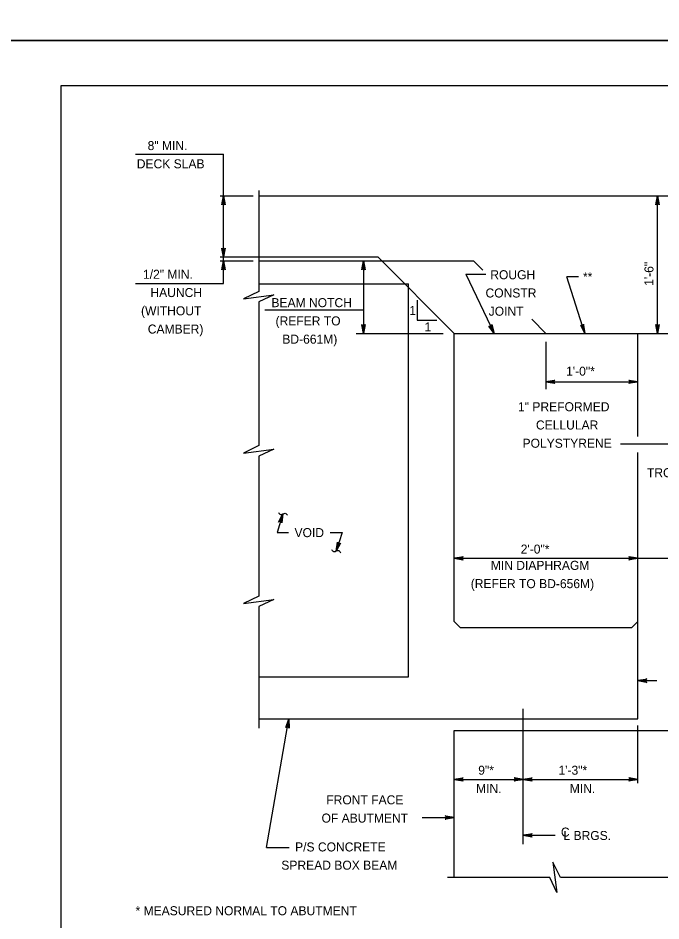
# Model space of a CAD drawing. Extents: x 636530 to 644067, y 294168 to 299122.
# Drawn here: x 639032.6 to 639246.3, y 295063.7 to 295364 of the extents above; entities that cross this region are included whole.
import ezdxf

# ---------------------------------------------------------------- set-up
doc = ezdxf.new("R2010")
doc.units = 0
doc.layers.add('1', color=7, linetype='Continuous')
doc.layers.add('PLT-BNDY', color=7, linetype='Continuous')

msp = doc.modelspace()

# ---------------------------------------------------------------- linework, layer by layer
at = {"layer": '1'}
for p, q in [((639832.78, 295341.48), (639046.78, 295341.48)), ((639046.78, 295341.48), (639046.78, 294777.48)), ((639071.67, 295318.67), (639100.84, 295318.67)), ((639100.84, 295284.5), (639100.84, 295318.67)), ((639112.67, 295306.66), (639112.67, 295273.07)), ((639099.73, 295304.82), (639110.72, 295304.82)), ((639112.67, 295304.82), (639291.18, 295304.82)), ((639245.17, 295259.1), (639245.17, 295304.82)), ((639099.73, 295284.5), (639110.72, 295284.5)), ((639099.73, 295283.23), (639110.72, 295283.23)), ((639100.84, 295275.67), (639100.84, 295284.5)), ((639106.89, 295284.5), (639152.19, 295284.5)), ((639112.67, 295283.23), (639153.46, 295283.23)), ((639147.38, 295283.23), (639147.38, 295259.1)), ((639177.59, 295259.1), (639152.19, 295284.5)), ((639153.46, 295283.23), (639183.94, 295283.23)), ((639187.05, 295280.12), (639183.94, 295283.23)), ((639181.39, 295278.76), (639190.86, 295259.1)), ((639181.39, 295278.76), (639188.12, 295278.76)), ((639218.89, 295277.94), (639215.04, 295277.94)), ((639220.95, 295259.1), (639215.04, 295277.94)), ((639071.67, 295275.67), (639100.84, 295275.67)), ((639112.67, 295275.61), (639162.35, 295275.61)), ((639162.35, 295144.8), (639162.35, 295275.61)), ((639165.21, 295270.12), (639165.21, 295263.54)), ((639112.67, 295269.55), (639112.67, 295221.79)), ((639114.61, 295266.93), (639147.38, 295266.93)), ((639165.21, 295263.54), (639171.79, 295263.54)), ((639208.07, 295259.1), (639203.4, 295263.77)), ((639145.03, 295259.1), (639173.94, 295259.1)), ((639177.59, 295259.1), (639238.55, 295259.1)), ((639177.59, 295163.21), (639177.59, 295259.1)), ((639238.55, 295259.1), (639313.34, 295259.1)), ((639238.55, 295224.8), (639238.55, 295259.1)), ((639208.07, 295256.29), (639208.07, 295240.58)), ((639208.07, 295242.99), (639238.55, 295242.99)), ((639232.79, 295222.35), (639251.5, 295222.35)), ((639238.55, 295163.21), (639238.55, 295219.43)), ((639112.67, 295218.27), (639112.67, 295171.73)), ((639120.6, 295199.03), (639118.68, 295192.82)), ((639118.68, 295192.82), (639122.48, 295192.82)), ((639136.31, 295192.82), (639140.3, 295192.82)), ((639140.3, 295192.82), (639138.38, 295186.61)), ((639177.59, 295184.27), (639296.46, 295184.27)), ((639112.67, 295168.21), (639112.67, 295127.8)), ((639177.59, 295163.21), (639179.5, 295161.31)), ((639236.65, 295161.31), (639238.55, 295163.21)), ((639238.55, 295130.83), (639238.55, 295163.21)), ((639179.5, 295161.31), (639236.65, 295161.31)), ((639112.67, 295144.8), (639162.35, 295144.8)), ((639238.55, 295143.58), (639244.95, 295143.58)), ((639200.45, 295089.18), (639200.45, 295134.26)), ((639112.67, 295130.83), (639238.55, 295130.83)), ((639115.2, 295088.03), (639122.64, 295130.83)), ((639177.59, 295127.02), (639253.79, 295127.02)), ((639177.59, 295078.06), (639177.59, 295127.02)), ((639238.55, 295109.45), (639238.55, 295128.65)), ((639177.59, 295110.74), (639200.45, 295110.74)), ((639200.45, 295110.74), (639238.55, 295110.74)), ((639166.96, 295098.04), (639177.59, 295098.04)), ((639200.45, 295092.14), (639211.08, 295092.14)), ((639115.2, 295088.03), (639122.72, 295088.03)), ((639209.35, 295078.06), (639175.31, 295078.06)), ((639261.49, 295078.06), (639212.87, 295078.06))]:
    msp.add_line(p, q, dxfattribs=at)
for points in [[(639100.84, 295304.82), (639101.4, 295301.84), (639101.32, 295301.95), (639101.24, 295302.07), (639101.14, 295302.12), (639101.04, 295302.18), (639100.94, 295302.2), (639100.84, 295302.22), (639100.74, 295302.2), (639100.64, 295302.18), (639100.54, 295302.12), (639100.44, 295302.07), (639100.36, 295301.95), (639100.28, 295301.84), (639100.84, 295304.82), (639100.36, 295301.95), (639100.44, 295302.07), (639100.84, 295304.82), (639100.54, 295302.12), (639100.64, 295302.18), (639100.84, 295304.82), (639100.74, 295302.2), (639100.84, 295302.22), (639100.84, 295304.82), (639100.94, 295302.2), (639101.04, 295302.18), (639100.84, 295304.82), (639101.14, 295302.12), (639101.24, 295302.07), (639100.84, 295304.82), (639101.32, 295301.95)], [(639245.17, 295304.82), (639245.73, 295301.84), (639245.57, 295302.07), (639245.37, 295302.18), (639245.17, 295302.22), (639244.97, 295302.18), (639244.77, 295302.07), (639244.61, 295301.84), (639245.17, 295304.82), (639244.77, 295302.07), (639244.97, 295302.18), (639245.17, 295304.82), (639245.17, 295302.22), (639245.37, 295302.18), (639245.17, 295304.82), (639245.57, 295302.07)], [(639100.84, 295284.5), (639100.28, 295287.48), (639100.36, 295287.36), (639100.44, 295287.25), (639100.54, 295287.19), (639100.64, 295287.13), (639100.74, 295287.11), (639100.84, 295287.1), (639100.94, 295287.11), (639101.04, 295287.13), (639101.14, 295287.19), (639101.24, 295287.25), (639101.32, 295287.36), (639101.4, 295287.48), (639100.84, 295284.5), (639101.32, 295287.36), (639101.24, 295287.25), (639100.84, 295284.5), (639101.14, 295287.19), (639101.04, 295287.13), (639100.84, 295284.5), (639100.94, 295287.11), (639100.84, 295287.1), (639100.84, 295284.5), (639100.74, 295287.11), (639100.64, 295287.13), (639100.84, 295284.5), (639100.54, 295287.19), (639100.44, 295287.25), (639100.84, 295284.5), (639100.36, 295287.36)], [(639100.84, 295283.23), (639101.4, 295280.25), (639101.32, 295280.36), (639101.24, 295280.48), (639101.14, 295280.54), (639101.04, 295280.59), (639100.94, 295280.61), (639100.84, 295280.63), (639100.74, 295280.61), (639100.64, 295280.59), (639100.54, 295280.54), (639100.44, 295280.48), (639100.36, 295280.36), (639100.28, 295280.25), (639100.84, 295283.23), (639100.36, 295280.36), (639100.44, 295280.48), (639100.84, 295283.23), (639100.54, 295280.54), (639100.64, 295280.59), (639100.84, 295283.23), (639100.74, 295280.61), (639100.84, 295280.63), (639100.84, 295283.23), (639100.94, 295280.61), (639101.04, 295280.59), (639100.84, 295283.23), (639101.14, 295280.54), (639101.24, 295280.48), (639100.84, 295283.23), (639101.32, 295280.36)], [(639147.38, 295283.23), (639147.94, 295280.25), (639147.86, 295280.36), (639147.78, 295280.48), (639147.68, 295280.54), (639147.58, 295280.59), (639147.48, 295280.61), (639147.38, 295280.63), (639147.28, 295280.61), (639147.18, 295280.59), (639147.08, 295280.54), (639146.98, 295280.48), (639146.9, 295280.36), (639146.82, 295280.25), (639147.38, 295283.23), (639146.9, 295280.36), (639146.98, 295280.48), (639147.38, 295283.23), (639147.08, 295280.54), (639147.18, 295280.59), (639147.38, 295283.23), (639147.28, 295280.61), (639147.38, 295280.63), (639147.38, 295283.23), (639147.48, 295280.61), (639147.58, 295280.59), (639147.38, 295283.23), (639147.68, 295280.54), (639147.78, 295280.48), (639147.38, 295283.23), (639147.86, 295280.36)], [(639112.67, 295273.07), (639107.48, 295270.53), (639117.63, 295271.91), (639112.67, 295269.55)], [(639147.38, 295259.1), (639146.82, 295262.08), (639146.9, 295261.97), (639146.98, 295261.85), (639147.08, 295261.79), (639147.18, 295261.73), (639147.28, 295261.72), (639147.38, 295261.7), (639147.48, 295261.72), (639147.58, 295261.73), (639147.68, 295261.79), (639147.78, 295261.85), (639147.86, 295261.97), (639147.94, 295262.08), (639147.38, 295259.1), (639147.86, 295261.97), (639147.78, 295261.85), (639147.38, 295259.1), (639147.68, 295261.79), (639147.58, 295261.73), (639147.38, 295259.1), (639147.48, 295261.72), (639147.38, 295261.7), (639147.38, 295259.1), (639147.28, 295261.72), (639147.18, 295261.73), (639147.38, 295259.1), (639147.08, 295261.79), (639146.98, 295261.85), (639147.38, 295259.1), (639146.9, 295261.97)], [(639190.86, 295259.1), (639189.06, 295261.54), (639189.18, 295261.47), (639189.3, 295261.4), (639189.42, 295261.39), (639189.53, 295261.38), (639189.63, 295261.41), (639189.73, 295261.44), (639189.81, 295261.5), (639189.89, 295261.56), (639189.96, 295261.66), (639190.02, 295261.75), (639190.04, 295261.89), (639190.07, 295262.03), (639190.86, 295259.1), (639190.04, 295261.89), (639190.02, 295261.75), (639190.86, 295259.1), (639189.96, 295261.66), (639189.89, 295261.56), (639190.86, 295259.1), (639189.81, 295261.5), (639189.73, 295261.44), (639190.86, 295259.1), (639189.63, 295261.41), (639189.53, 295261.38), (639190.86, 295259.1), (639189.42, 295261.39), (639189.3, 295261.4), (639190.86, 295259.1), (639189.18, 295261.47)], [(639220.95, 295259.1), (639220.59, 295262.11), (639220.55, 295261.98), (639220.5, 295261.84), (639220.43, 295261.76), (639220.35, 295261.67), (639220.26, 295261.63), (639220.17, 295261.58), (639220.07, 295261.57), (639219.97, 295261.55), (639219.85, 295261.58), (639219.74, 295261.61), (639219.63, 295261.69), (639219.52, 295261.78), (639220.95, 295259.1), (639219.63, 295261.69), (639219.74, 295261.61), (639220.95, 295259.1), (639219.85, 295261.58), (639219.97, 295261.55), (639220.95, 295259.1), (639220.07, 295261.57), (639220.17, 295261.58), (639220.95, 295259.1), (639220.26, 295261.63), (639220.35, 295261.67), (639220.95, 295259.1), (639220.43, 295261.76), (639220.5, 295261.84), (639220.95, 295259.1), (639220.55, 295261.98)], [(639245.17, 295259.1), (639244.61, 295262.08), (639244.77, 295261.85), (639244.97, 295261.73), (639245.17, 295261.7), (639245.37, 295261.73), (639245.57, 295261.85), (639245.73, 295262.08), (639245.17, 295259.1), (639245.57, 295261.85), (639245.37, 295261.73), (639245.17, 295259.1), (639245.17, 295261.7), (639244.97, 295261.73), (639245.17, 295259.1), (639244.77, 295261.85)], [(639208.07, 295242.99), (639211.06, 295243.55), (639210.94, 295243.47), (639210.83, 295243.39), (639210.77, 295243.29), (639210.71, 295243.19), (639210.69, 295243.09), (639210.67, 295242.99), (639210.69, 295242.89), (639210.71, 295242.79), (639210.77, 295242.69), (639210.83, 295242.59), (639210.94, 295242.51), (639211.06, 295242.43), (639208.07, 295242.99), (639210.94, 295242.51), (639210.83, 295242.59), (639208.07, 295242.99), (639210.77, 295242.69), (639210.71, 295242.79), (639208.07, 295242.99), (639210.69, 295242.89), (639210.67, 295242.99), (639208.07, 295242.99), (639210.69, 295243.09), (639210.71, 295243.19), (639208.07, 295242.99), (639210.77, 295243.29), (639210.83, 295243.39), (639208.07, 295242.99), (639210.94, 295243.47)], [(639238.55, 295242.99), (639235.57, 295242.43), (639235.69, 295242.51), (639235.8, 295242.59), (639235.86, 295242.69), (639235.92, 295242.79), (639235.94, 295242.89), (639235.95, 295242.99), (639235.94, 295243.09), (639235.92, 295243.19), (639235.86, 295243.29), (639235.8, 295243.39), (639235.69, 295243.47), (639235.57, 295243.55), (639238.55, 295242.99), (639235.69, 295243.47), (639235.8, 295243.39), (639238.55, 295242.99), (639235.86, 295243.29), (639235.92, 295243.19), (639238.55, 295242.99), (639235.94, 295243.09), (639235.95, 295242.99), (639238.55, 295242.99), (639235.94, 295242.89), (639235.92, 295242.79), (639238.55, 295242.99), (639235.86, 295242.69), (639235.8, 295242.59), (639238.55, 295242.99), (639235.69, 295242.51)], [(639112.67, 295221.79), (639107.48, 295219.25), (639117.63, 295220.63), (639112.67, 295218.27)], [(639120.6, 295199.03), (639120.26, 295196.02), (639120.17, 295196.29), (639120.02, 295196.46), (639119.84, 295196.55), (639119.64, 295196.58), (639119.41, 295196.52), (639119.19, 295196.35), (639120.6, 295199.03), (639119.41, 295196.52), (639119.64, 295196.58), (639120.6, 295199.03), (639119.84, 295196.55), (639120.02, 295196.46), (639120.6, 295199.03), (639120.17, 295196.29)], [(639138.38, 295186.61), (639138.73, 295189.62), (639138.81, 295189.36), (639138.97, 295189.19), (639139.15, 295189.09), (639139.35, 295189.07), (639139.58, 295189.12), (639139.8, 295189.29), (639138.38, 295186.61), (639139.58, 295189.12), (639139.35, 295189.07), (639138.38, 295186.61), (639139.15, 295189.09), (639138.97, 295189.19), (639138.38, 295186.61), (639138.81, 295189.36)], [(639177.59, 295184.27), (639180.58, 295184.83), (639180.46, 295184.75), (639180.35, 295184.67), (639180.29, 295184.57), (639180.23, 295184.47), (639180.21, 295184.37), (639180.19, 295184.27), (639180.21, 295184.17), (639180.23, 295184.07), (639180.29, 295183.97), (639180.35, 295183.87), (639180.46, 295183.79), (639180.58, 295183.71), (639177.59, 295184.27), (639180.46, 295183.79), (639180.35, 295183.87), (639177.59, 295184.27), (639180.29, 295183.97), (639180.23, 295184.07), (639177.59, 295184.27), (639180.21, 295184.17), (639180.19, 295184.27), (639177.59, 295184.27), (639180.21, 295184.37), (639180.23, 295184.47), (639177.59, 295184.27), (639180.29, 295184.57), (639180.35, 295184.67), (639177.59, 295184.27), (639180.46, 295184.75)], [(639238.55, 295184.27), (639235.57, 295183.71), (639235.69, 295183.79), (639235.8, 295183.87), (639235.86, 295183.97), (639235.92, 295184.07), (639235.94, 295184.17), (639235.95, 295184.27), (639235.94, 295184.37), (639235.92, 295184.47), (639235.86, 295184.57), (639235.8, 295184.67), (639235.69, 295184.75), (639235.57, 295184.83), (639238.55, 295184.27), (639235.69, 295184.75), (639235.8, 295184.67), (639238.55, 295184.27), (639235.86, 295184.57), (639235.92, 295184.47), (639238.55, 295184.27), (639235.94, 295184.37), (639235.95, 295184.27), (639238.55, 295184.27), (639235.94, 295184.17), (639235.92, 295184.07), (639238.55, 295184.27), (639235.86, 295183.97), (639235.8, 295183.87), (639238.55, 295184.27), (639235.69, 295183.79)], [(639112.67, 295171.73), (639107.48, 295169.2), (639117.63, 295170.58), (639112.67, 295168.21)], [(639238.55, 295143.58), (639241.54, 295144.14), (639241.42, 295144.06), (639241.31, 295143.98), (639241.25, 295143.88), (639241.19, 295143.78), (639241.17, 295143.68), (639241.15, 295143.58), (639241.17, 295143.48), (639241.19, 295143.38), (639241.25, 295143.28), (639241.31, 295143.18), (639241.42, 295143.1), (639241.54, 295143.02), (639238.55, 295143.58), (639241.42, 295143.1), (639241.31, 295143.18), (639238.55, 295143.58), (639241.25, 295143.28), (639241.19, 295143.38), (639238.55, 295143.58), (639241.17, 295143.48), (639241.15, 295143.58), (639238.55, 295143.58), (639241.17, 295143.68), (639241.19, 295143.78), (639238.55, 295143.58), (639241.25, 295143.88), (639241.31, 295143.98), (639238.55, 295143.58), (639241.42, 295144.06)], [(639122.64, 295130.83), (639122.68, 295127.79), (639122.62, 295127.92), (639122.56, 295128.05), (639122.48, 295128.12), (639122.39, 295128.2), (639122.29, 295128.23), (639122.2, 295128.27), (639122.1, 295128.27), (639121.99, 295128.27), (639121.88, 295128.23), (639121.78, 295128.19), (639121.68, 295128.09), (639121.58, 295127.99), (639122.64, 295130.83), (639121.68, 295128.09), (639121.78, 295128.19), (639122.64, 295130.83), (639121.88, 295128.23), (639121.99, 295128.27), (639122.64, 295130.83), (639122.1, 295128.27), (639122.2, 295128.27), (639122.64, 295130.83), (639122.29, 295128.23), (639122.39, 295128.2), (639122.64, 295130.83), (639122.48, 295128.12), (639122.56, 295128.05), (639122.64, 295130.83), (639122.62, 295127.92)], [(639177.59, 295110.74), (639180.58, 295111.3), (639180.46, 295111.22), (639180.35, 295111.14), (639180.29, 295111.04), (639180.23, 295110.94), (639180.21, 295110.84), (639180.19, 295110.74), (639180.21, 295110.64), (639180.23, 295110.54), (639180.29, 295110.44), (639180.35, 295110.34), (639180.46, 295110.26), (639180.58, 295110.18), (639177.59, 295110.74), (639180.46, 295110.26), (639180.35, 295110.34), (639177.59, 295110.74), (639180.29, 295110.44), (639180.23, 295110.54), (639177.59, 295110.74), (639180.21, 295110.64), (639180.19, 295110.74), (639177.59, 295110.74), (639180.21, 295110.84), (639180.23, 295110.94), (639177.59, 295110.74), (639180.29, 295111.04), (639180.35, 295111.14), (639177.59, 295110.74), (639180.46, 295111.22)], [(639200.45, 295110.74), (639197.47, 295110.18), (639197.59, 295110.26), (639197.7, 295110.34), (639197.76, 295110.44), (639197.82, 295110.54), (639197.84, 295110.64), (639197.85, 295110.74), (639197.84, 295110.84), (639197.82, 295110.94), (639197.76, 295111.04), (639197.7, 295111.14), (639197.59, 295111.22), (639197.47, 295111.3), (639200.45, 295110.74), (639197.59, 295111.22), (639197.7, 295111.14), (639200.45, 295110.74), (639197.76, 295111.04), (639197.82, 295110.94), (639200.45, 295110.74), (639197.84, 295110.84), (639197.85, 295110.74), (639200.45, 295110.74), (639197.84, 295110.64), (639197.82, 295110.54), (639200.45, 295110.74), (639197.76, 295110.44), (639197.7, 295110.34), (639200.45, 295110.74), (639197.59, 295110.26)], [(639200.45, 295110.74), (639203.44, 295111.3), (639203.32, 295111.22), (639203.21, 295111.14), (639203.15, 295111.04), (639203.09, 295110.94), (639203.07, 295110.84), (639203.05, 295110.74), (639203.07, 295110.64), (639203.09, 295110.54), (639203.15, 295110.44), (639203.21, 295110.34), (639203.32, 295110.26), (639203.44, 295110.18), (639200.45, 295110.74), (639203.32, 295110.26), (639203.21, 295110.34), (639200.45, 295110.74), (639203.15, 295110.44), (639203.09, 295110.54), (639200.45, 295110.74), (639203.07, 295110.64), (639203.05, 295110.74), (639200.45, 295110.74), (639203.07, 295110.84), (639203.09, 295110.94), (639200.45, 295110.74), (639203.15, 295111.04), (639203.21, 295111.14), (639200.45, 295110.74), (639203.32, 295111.22)], [(639238.55, 295110.74), (639235.57, 295110.18), (639235.69, 295110.26), (639235.8, 295110.34), (639235.86, 295110.44), (639235.92, 295110.54), (639235.94, 295110.64), (639235.95, 295110.74), (639235.94, 295110.84), (639235.92, 295110.94), (639235.86, 295111.04), (639235.8, 295111.14), (639235.69, 295111.22), (639235.57, 295111.3), (639238.55, 295110.74), (639235.69, 295111.22), (639235.8, 295111.14), (639238.55, 295110.74), (639235.86, 295111.04), (639235.92, 295110.94), (639238.55, 295110.74), (639235.94, 295110.84), (639235.95, 295110.74), (639238.55, 295110.74), (639235.94, 295110.64), (639235.92, 295110.54), (639238.55, 295110.74), (639235.86, 295110.44), (639235.8, 295110.34), (639238.55, 295110.74), (639235.69, 295110.26)], [(639177.59, 295098.04), (639174.61, 295097.48), (639174.73, 295097.56), (639174.84, 295097.64), (639174.9, 295097.74), (639174.96, 295097.84), (639174.98, 295097.94), (639174.99, 295098.04), (639174.98, 295098.14), (639174.96, 295098.24), (639174.9, 295098.34), (639174.84, 295098.44), (639174.73, 295098.52), (639174.61, 295098.6), (639177.59, 295098.04), (639174.73, 295098.52), (639174.84, 295098.44), (639177.59, 295098.04), (639174.9, 295098.34), (639174.96, 295098.24), (639177.59, 295098.04), (639174.98, 295098.14), (639174.99, 295098.04), (639177.59, 295098.04), (639174.98, 295097.94), (639174.96, 295097.84), (639177.59, 295098.04), (639174.9, 295097.74), (639174.84, 295097.64), (639177.59, 295098.04), (639174.73, 295097.56)], [(639200.45, 295092.14), (639203.44, 295092.69), (639203.32, 295092.62), (639203.21, 295092.54), (639203.15, 295092.44), (639203.09, 295092.34), (639203.07, 295092.24), (639203.05, 295092.14), (639203.07, 295092.04), (639203.09, 295091.94), (639203.15, 295091.84), (639203.21, 295091.74), (639203.32, 295091.66), (639203.44, 295091.58), (639200.45, 295092.14), (639203.32, 295091.66), (639203.21, 295091.74), (639200.45, 295092.14), (639203.15, 295091.84), (639203.09, 295091.94), (639200.45, 295092.14), (639203.07, 295092.04), (639203.05, 295092.14), (639200.45, 295092.14), (639203.07, 295092.24), (639203.09, 295092.34), (639200.45, 295092.14), (639203.15, 295092.44), (639203.21, 295092.54), (639200.45, 295092.14), (639203.32, 295092.62)], [(639212.87, 295078.06), (639210.33, 295083.24), (639211.71, 295073.1), (639209.35, 295078.06)]]:
    msp.add_lwpolyline(points, dxfattribs=at)
for points in [[(639119.12, 295199.53), (639119.81, 295198.83), (639121.4, 295199.24), (639122.1, 295198.6)], [(639139.86, 295186.12), (639139.17, 295186.81), (639137.58, 295186.4), (639136.89, 295187.05)]]:
    msp.add_spline(points, degree=3, dxfattribs=at)
at = {"layer": 'PLT-BNDY'}
for points in [[(639006.78, 295950.48), (639847.78, 295950.48), (639847.78, 295356.48), (639006.78, 295356.48)], [(639006.78, 295356.48), (639847.78, 295356.48), (639847.78, 294762.48), (639006.78, 294762.48)]]:
    msp.add_lwpolyline(points, close=True, dxfattribs=at)

# ---------------------------------------------------------------- texts
at = {"layer": '1'}
for s, rotation, p in [('8" MIN.', 360, (639075.66, 295320.06)), ('DECK SLAB', 360, (639072.05, 295313.99)), ('1\'-6"', 90, (639243.8, 295274.9)), ('1/2" MIN.', 360, (639074.12, 295277.24)), ('HAUNCH', 360, (639076.58, 295271.17)), ('(WITHOUT', 360, (639073.46, 295265.1)), ('CAMBER)', 360, (639075.7, 295259.03))]:
    msp.add_text(s, height=3, rotation=rotation, dxfattribs=at).set_placement(p)
for s, p in [('ROUGH', (639189.55, 295277.1)), ('**', (639220.36, 295276.42)), ('CONSTR', (639187.97, 295271.03)), ('BEAM NOTCH', (639116.81, 295267.81)), ('1', (639162.65, 295265.24)), (' JOINT', (639187.91, 295264.96)), ('(REFER TO', (639118.18, 295261.74)), ('1', (639167.71, 295259.73)), ('BD-661M)', (639120.43, 295255.67)), ('1\'-0"*', (639214.76, 295245.02)), ('1" PREFORMED', (639198.78, 295233.19)), ('CELLULAR', (639204.74, 295227.12)), ('POLYSTYRENE', (639200.28, 295221.05)), ('TROWEL SMOOTH', (639241.64, 295211.25)), ('VOID', (639124.48, 295191.32)), ('2\'-0"*', (639199.67, 295185.84)), ('MIN DIAPHRAGM', (639189.73, 295180.43)), ('(REFER TO BD-656M)', (639183.06, 295174.35)), ('9"*', (639185.55, 295112.29)), ('1\'-3"*', (639212.22, 295112.29)), ('MIN.', (639184.84, 295106.22)), ('MIN.', (639215.98, 295106.22)), ('FRONT FACE', (639135.04, 295102.44)), ('OF ABUTMENT', (639133.47, 295096.37)), ('C', (639213.03, 295091.71)), ('L BRGS.', (639213.88, 295090.58)), ('P/S CONCRETE', (639124.68, 295086.77)), ('SPREAD BOX BEAM', (639120.1, 295080.7)), ('* MEASURED NORMAL TO ABUTMENT', (639071.63, 295065.55))]:
    msp.add_text(s, height=3, dxfattribs=at).set_placement(p)

doc.saveas('drawing.dxf')
